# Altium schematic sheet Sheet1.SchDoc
size A4
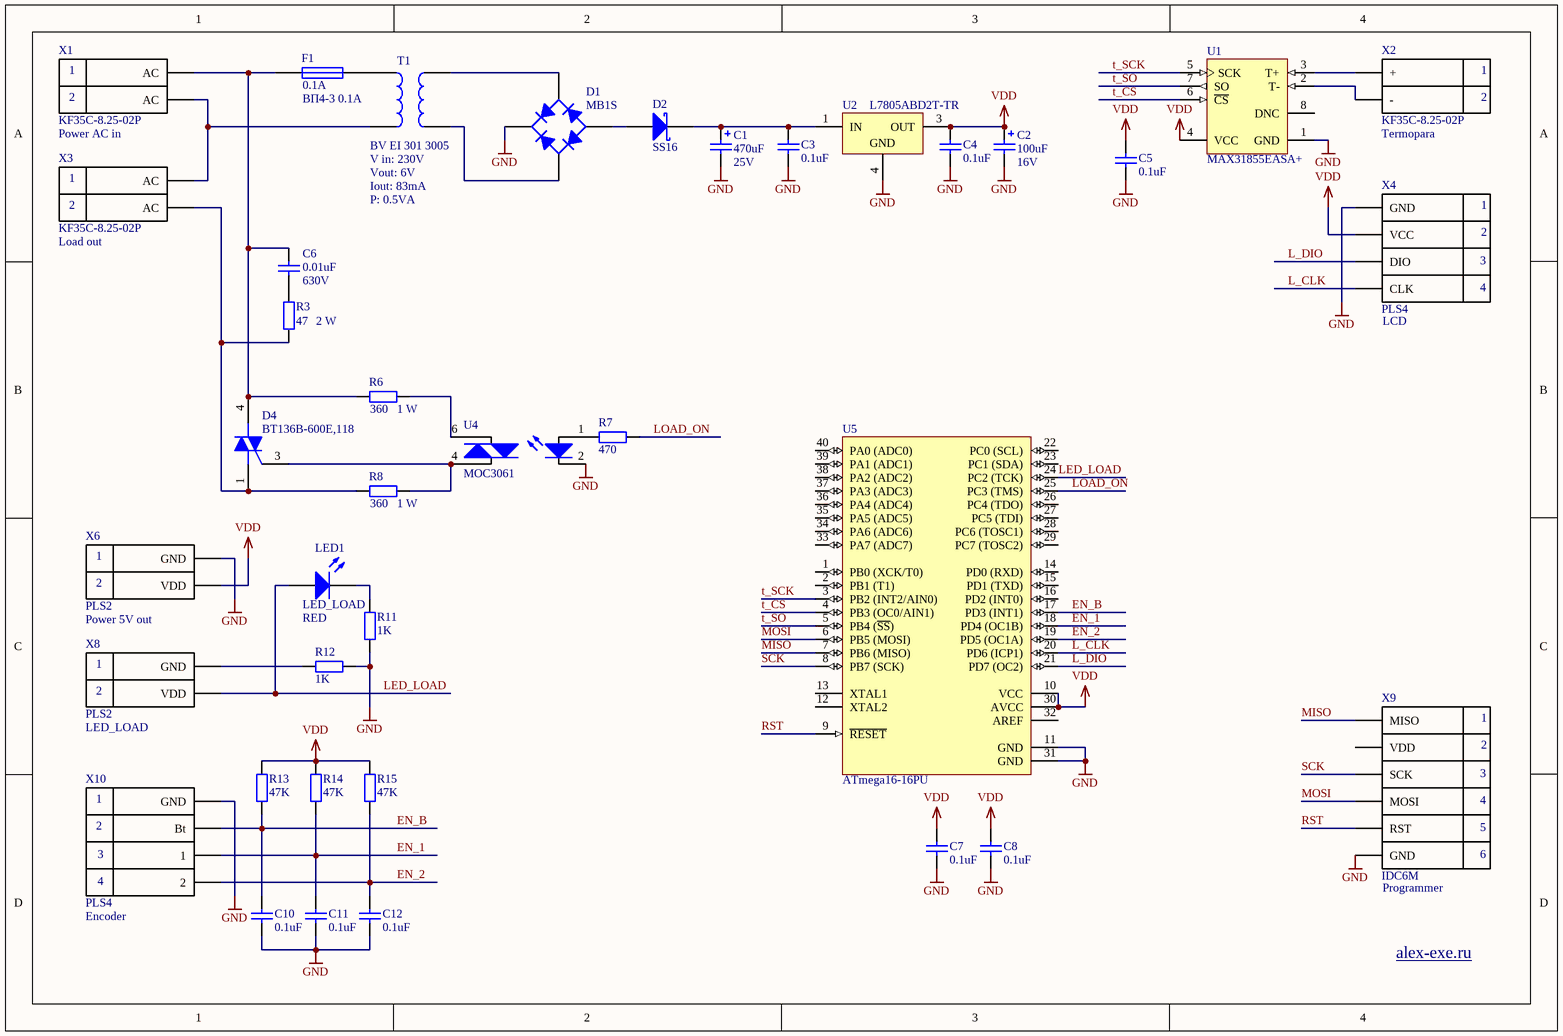
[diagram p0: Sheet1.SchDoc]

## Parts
C1  470uF  Voltage: 25V  [CAP-SMD-10.5]
C2  100uF  Voltage: 16V  [Tantal_C]
C3  0.1uF  [CAP-0603]
C4  0.1uF  [CAP-0603]
C5  0.1uF  [CAP-0603]
C6  0.01uF  Voltage: 630V  [К73-17-630]
C7  0.1uF  [CAP-0603]
C8  0.1uF  [CAP-0603]
C10  0.1uF  [CAP-0603]
C11  0.1uF  [CAP-0603]
C12  0.1uF  [CAP-0603]
D1  MB1S  [MBS]
D2  SS16  [SMA]
D4  BT136B-600E,118  [TO-263_N]
F1  0.1A  Marka: ВП4-3 0.1А  [PIN-W2/E2.8]
LED1  LED_LOAD  Color: RED  [LED0603 - red]
R3  47  Power: 2 W  [resistor 0.125W 10.16mm]
R6  360  Power: 1 W  [res-2512]
R7  470  [RES-0603]
R8  360  Power: 1 W  [res-2512]
R11  1K  [RES-0603]
R12  1K  [RES-0603]
R13  47K  [RES-0603]
R14  47K  [RES-0603]
R15  47K  [RES-0603]
T1  Marka: BV EI 301 3005  V in: 230V  Vout: 6V  Iout: 83mA  P: 0.5VA  [BV EI Schema 1]  (hidden comment: Trans)
U1  MAX31855EASA+  [MAXM-S8+4_N]
U2  L7805ABD2T-TR  [TO-263_N]
U4  MOC3061  [DIP6]
U5  ATmega16-16PU  [40P6]
X1  KF35C-8.25-02P  Name: Power AC in  [KF35C-8.25-02P]
X2  KF35C-8.25-02P  Name: Termopara  [KF35C-8.25-02P]
X3  KF35C-8.25-02P  Name: Load out  [KF35C-8.25-02P]
X4  PLS4  Name: LCD  [PLS4]
X6  PLS2  Name: Power 5V out  [PLS2]
X8  PLS2  Name: LED_LOAD  [PLS2]
X9  IDC6M  Name: Programmer  [IDC6M]
X10  PLS4  Name: Encoder  [PLS4]

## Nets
GND: C1.2 C2.2 C3.1 C4.1 C5.1 C7.1 C8.1 C10.1 C11.1 C12.1 D1.2(K) R11.1 R12.2 U1.1(GND) U2.4(GND) U4.2(K) U5.11(GND) U5.31(GND) X4.1(GND) X6.1(GND) X9.6(GND) X10.1(GND)
VDD: C2.1 C4.2 C5.2 C7.2 C8.2 R13.2 R14.2 R15.2 U1.4(VCC) U2.3(OUT) U5.10(VCC) U5.30(AVCC) X4.2(VCC) X6.2(VDD)
EN_1: C11.2 R14.1 U5.18(PD4_(OC1B)) X10.3(1)
EN_2: C12.2 R15.1 U5.19(PD5_(OC1A)) X10.4(2)
EN_B: C10.2 R13.1 U5.17(PD3_(INT1)) X10.2(Bt)
L_CLK: U5.20(PD6_(ICP1)) X4.4(CLK)
L_DIO: U5.21(PD7_(OC2)) X4.3(DIO)
LED_LOAD: LED1.1(A) U5.24(PC2_(TCK)) X8.2(VDD)
LOAD_ON: R7.1 U5.25(PC3_(TMS))
MISO: U5.7(PB6_(MISO)) X9.1(MISO)
MOSI: U5.6(PB5_(MOSI)) X9.4(MOSI)
RST: U5.9(~{RESET}) X9.5(RST)
SCK: U5.8(PB7_(SCK)) X9.3(SCK)
t_CS: U1.6(~{CS}) U5.4(PB3_(OC0/AIN1))
t_SCK: U1.5(SCK) U5.3(PB2_(INT2/AIN0))
t_SO: U1.7(SO) U5.5(PB4_(~{SS}))
NetC1_1: C1.1 C3.2 D2.1(K) U2.1(IN)
NetC6_1: C6.1 R3.1
NetC6_2: C6.2 D4.4(MT2) F1.1 R6.2 X1.1(AC)
NetD1_1: D1.1(A) D2.2(A)
NetD1_3: D1.3(C) T1.9
NetD1_4: D1.4(C) T1.7
NetD4_1: D4.1(MT1) R3.2 R8.2 X3.2(AC)
NetD4_3: D4.3(G) R8.1 U4.4(M)
NetF1_2: F1.2 T1.1
NetLED1_2: LED1.2(K) R11.2
NetR6_1: R6.1 U4.6(M)
NetR7_2: R7.2 U4.1(A)
NetR12_1: R12.1 X8.1(GND)
NetT1_5: T1.5 X1.2(AC) X3.1(AC)
NetU1_2: U1.2(T-) X2.2(-)
NetU1_3: U1.3(T+) X2.1(+)

Not connected (* = marked no-connect by the designer): U1 8(DNC); U5 1(PB0_(XCK/T0)) 2(PB1_(T1)) 12(XTAL2) 13(XTAL1) 14(PD0_(RXD)) 15(PD1_(TXD)) 16(PD2_(INT0)) 22(PC0_(SCL)) 23(PC1_(SDA)) 26(PC4_(TDO)) 27(PC5_(TDI)) 28(PC6_(TOSC1)) 29(PC7_(TOSC2)) 32(AREF) 33(PA7_(ADC7)) 34(PA6_(ADC6)) 35(PA5_(ADC5)) 36(PA4_(ADC4)) 37(PA3_(ADC3)) 38(PA2_(ADC2)) 39(PA1_(ADC1)) 40(PA0_(ADC0)); X9 2(VDD)

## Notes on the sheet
- alex-exe.ru <http://alex-exe.ru>

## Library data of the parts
C1 C2 = Cap Pol: Polarized Capacitor (Axial); type: 5 Capacitor; pads SMD: 2; proma ID: 161877; Marka: 293D107X9010C2TE3
C3-C5 C7 C8 C10-C12 = Cap: Capacitor; Voltage: 25V; type: 5 Capacitor; pads SMD: 2; proma ID: 126354; Marka: CC0603KRX7R9BB104
C6 = Cap: Capacitor; type: 5 Capacitor; pads SMD: 2
D1 = Bridge1: Full Wave Diode Bridge; type: 2 Semiconductor; pads SMD: 4; proma ID: 214701
D2 = D Schottky: Schottky Diode; type: 2 Semiconductor
D4 = BTA12-600C4G: Triacs, Silicon Bidirectional Thyristor, 3-Pin TO-220, Pb-Free, Tube; Manufacturer: On Semiconductor; IT(RMS) Max (A): 12; ITSM Max (A): 120; pads SMD: 3; type: 2 Semiconductor; proma ID: 185050
F1 = Fuse 1: Fuse; type: 9 Installation
LED1 = LED0: Typical INFRARED GaAs LED; pads SMD: 2; type: 3 Indicator; proma ID: 324327
R3 R6-R8 R11 R12 = Res: pads SMD: 2
R13-R15 = Res: pads SMD: 2; Marka: RC0603JR-0747KL
T1 = Trans: Transformer; pin to pad: 2>7 3>5 4>9; type: 9 Installation; type: 6 Iductor; proma ID: 74757
U1 = MAX31855EASA+: Cold Junction Compensated Thermocouple to Digital Converter, 14 Bits Temperature Resolution, -40 to 125 degC, 8-Pin SOIC (S8+4), Pb-Free; Functions: Thermocouple-to-Digital Converter; Interface: SPI; Parasite Pwr.: No; pads SMD: 8; proma ID: 319597
U2 = L7805ABD2T-TR: Positive Voltage Regulator, 3-Pin D2PAK, Tape and Reel; pads SMD: 3; proma ID: 130104
U4 = MOC3021SM: Опто транзистор x1 5.3kV 70V 0.05A; pads SMD: 6
U5 = ATmega16-16PU: 8-bit AVR Microcontroller, 4.5-5.5V, 16KB Flash, 512 Bytes EEPROM, 1KB SRAM, 40-pin PDIP, Industrial Grade (-40°C to 85°C), Pb-Free
X1-X3 = PLS2
X9 = IDC6M: pads THT: 6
